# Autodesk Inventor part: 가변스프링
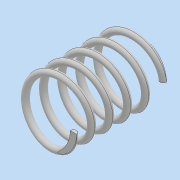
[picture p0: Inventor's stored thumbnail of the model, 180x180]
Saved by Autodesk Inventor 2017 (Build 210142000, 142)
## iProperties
Part Number: 가변스프링
Material: 일반
Document SubType Name: Modeling
Designer: MRC
Density: 1 g/cm^3
Appearance: 기본값
Mass: 0.874626 g
Surface Area: 17.7559 cm^2
Volume: 0.874626 cm^3
Author: MRC
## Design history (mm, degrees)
sketch "스케치1"
  geometry: L1 (0, 0)-(0, 28.5); L2 (0, 0)-(9, 0); L3 (9, 28.5)-(0, 28.5); C1 r 1 at (9, 0)
  constraints: 6 end point, 1 centre point, 1 horizontal, 1 horizontal alignment, 1 vertical
  dimensions: "d0" = 28.5 distance of L1.start L1.end (derived); "d1" = 2 diameter of C1; "d3" = 18 diameter of L2.end L1
feature "코일1" sketch "스케치1" pitch "d4" = 10; turns "d6" = 5; dims "d5" = 28.5 (= d0), "d7" = 0, angle "d8" = 90 deg, angle "d9" = 90 deg, "d10" = 0, "d11" = 0
sketch "스케치2"
  geometry: L1 (28.5, 15)-(0, 15); L2 (0, 15)-(0, -15); L3 (0, -15)-(28.5, -15); L4 (28.5, -15)-(28.5, 15); 2 further points
  constraints: 8 end point, 2 parallel, 1 coincident, 1 horizontal, 1 midpoint, 1 perpendicular
  dimensions: "d12" = 30 distance of L3.end L1.start; "d16" = 28.5 distance of L1.start L1.end (= d0)
extrude "돌출1" sketch "스케치2" stored distance "d14" = 0; taper "d15" = 0 deg
node "솔리드1"
